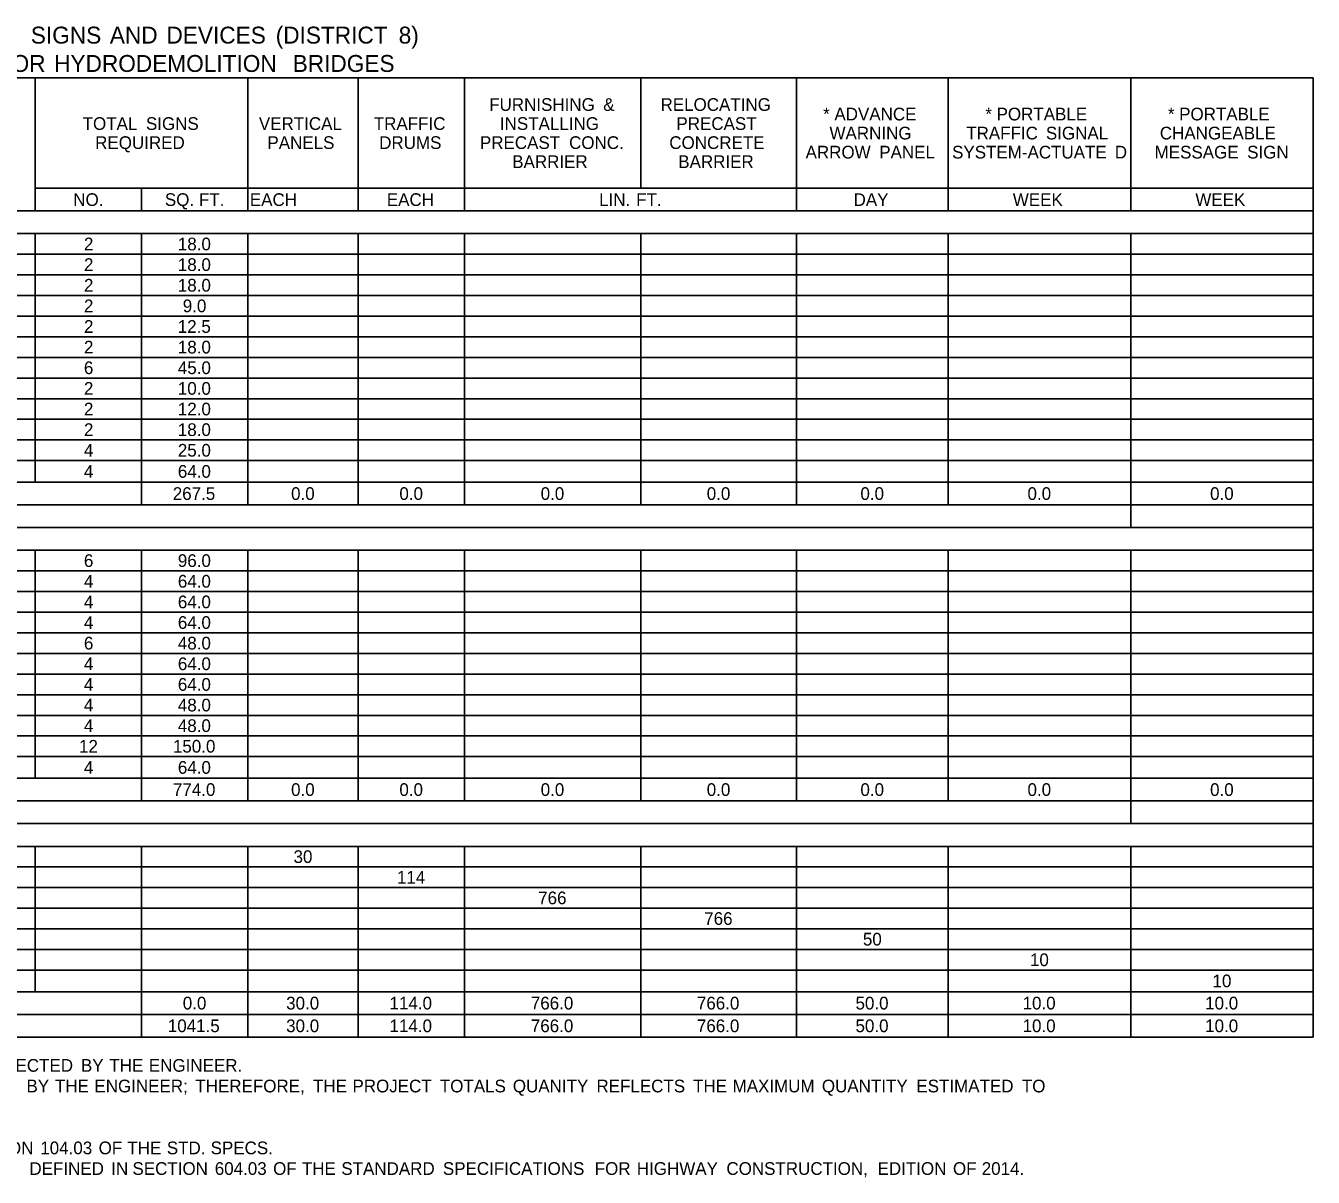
# Model space of a CAD drawing. Extents: x 540541 to 1930787, y -1948574 to 596640.
# Drawn here: x 542992 to 543601, y -1946816 to -1946271 of the extents above; entities that cross this region are included whole.
import ezdxf

# ---------------------------------------------------------------- set-up
doc = ezdxf.new("R2010")
doc.units = 0
doc.layers.add('Default', color=7, linetype='Continuous')

msp = doc.modelspace()

# ---------------------------------------------------------------- linework, layer by layer
at = {"layer": 'Default'}
for p, q in [((542470.09, -1946295.96), (543600.6, -1946295.96)), ((542996.59, -1946358.85), (542996.59, -1946295.96)), ((543097.02, -1946358.85), (543097.02, -1946295.96)), ((543149.18, -1946358.85), (543149.18, -1946295.96)), ((543199.39, -1946358.85), (543199.39, -1946295.96)), ((543282.75, -1946348.12), (543282.75, -1946295.96)), ((543356.37, -1946358.85), (543356.37, -1946295.96)), ((543428.03, -1946358.85), (543428.03, -1946295.96)), ((543514.32, -1946358.85), (543514.32, -1946295.96)), ((543600.6, -1946348.12), (543600.6, -1946295.96)), ((542996.59, -1946348.12), (543600.6, -1946348.12)), ((543046.8, -1946358.85), (543046.8, -1946348.12)), ((543149.18, -1946358.85), (543149.18, -1946348.12)), ((543514.32, -1946358.85), (543514.32, -1946348.12)), ((543600.6, -1946369.57), (543600.6, -1946348.12)), ((542470.09, -1946358.85), (543600.6, -1946358.85)), ((542938.58, -1946358.85), (543600.6, -1946358.85)), ((542470.09, -1946369.57), (543600.6, -1946369.57)), ((542996.59, -1946487.06), (542996.59, -1946369.57)), ((543046.8, -1946487.06), (543046.8, -1946369.57)), ((543046.8, -1946497.78), (543046.8, -1946369.57)), ((543097.02, -1946497.78), (543097.02, -1946369.57)), ((543097.02, -1946497.78), (543097.02, -1946369.57)), ((543149.18, -1946447.57), (543149.18, -1946369.57)), ((543149.18, -1946497.78), (543149.18, -1946369.57)), ((543199.39, -1946497.78), (543199.39, -1946369.57)), ((543199.39, -1946497.78), (543199.39, -1946369.57)), ((543282.75, -1946497.78), (543282.75, -1946369.57)), ((543282.75, -1946497.78), (543282.75, -1946369.57)), ((543356.37, -1946497.78), (543356.37, -1946369.57)), ((543356.37, -1946497.78), (543356.37, -1946369.57)), ((543428.03, -1946497.78), (543428.03, -1946369.57)), ((543514.32, -1946508.51), (543514.32, -1946369.57)), ((543600.6, -1946508.51), (543600.6, -1946369.57)), ((542470.09, -1946379.32), (543600.6, -1946379.32)), ((542470.09, -1946389.07), (543600.6, -1946389.07)), ((542470.09, -1946398.82), (543600.6, -1946398.82)), ((542470.09, -1946408.57), (543600.6, -1946408.57)), ((542470.09, -1946418.32), (543600.6, -1946418.32)), ((542470.09, -1946428.07), (543600.6, -1946428.07)), ((542470.09, -1946437.82), (543600.6, -1946437.82)), ((542470.09, -1946447.57), (543600.6, -1946447.57)), ((542470.09, -1946457.32), (543600.6, -1946457.32)), ((543149.18, -1946497.78), (543149.18, -1946457.32)), ((542470.09, -1946467.07), (543600.6, -1946467.07)), ((542470.09, -1946476.82), (543600.6, -1946476.82)), ((542470.09, -1946487.06), (543600.6, -1946487.06)), ((542470.09, -1946487.06), (543600.6, -1946487.06)), ((543428.03, -1946497.78), (543428.03, -1946487.06)), ((542470.09, -1946497.78), (543600.6, -1946497.78)), ((543514.32, -1946508.51), (543514.32, -1946497.78)), ((542470.09, -1946508.51), (543600.6, -1946508.51)), ((543600.6, -1946519.23), (543600.6, -1946508.51)), ((542470.09, -1946519.23), (543600.6, -1946519.23)), ((542996.59, -1946626.97), (542996.59, -1946519.23)), ((543046.8, -1946637.7), (543046.8, -1946519.23)), ((543046.8, -1946637.7), (543046.8, -1946519.23)), ((543097.02, -1946637.7), (543097.02, -1946519.23)), ((543097.02, -1946637.7), (543097.02, -1946519.23)), ((543149.18, -1946637.7), (543149.18, -1946519.23)), ((543149.18, -1946637.7), (543149.18, -1946519.23)), ((543199.39, -1946637.7), (543199.39, -1946519.23)), ((543199.39, -1946637.7), (543199.39, -1946519.23)), ((543282.75, -1946637.7), (543282.75, -1946519.23)), ((543282.75, -1946637.7), (543282.75, -1946519.23)), ((543356.37, -1946637.7), (543356.37, -1946519.23)), ((543356.37, -1946637.7), (543356.37, -1946519.23)), ((543428.03, -1946637.7), (543428.03, -1946519.23)), ((543514.32, -1946648.42), (543514.32, -1946519.23)), ((543600.6, -1946749.33), (543600.6, -1946519.23)), ((542470.09, -1946528.98), (543600.6, -1946528.98)), ((542470.09, -1946538.73), (543600.6, -1946538.73)), ((542470.09, -1946548.48), (543600.6, -1946548.48)), ((542470.09, -1946558.23), (543600.6, -1946558.23)), ((542470.09, -1946567.98), (543600.6, -1946567.98)), ((542470.09, -1946577.73), (543600.6, -1946577.73)), ((542470.09, -1946587.48), (543600.6, -1946587.48)), ((542470.09, -1946597.23), (543600.6, -1946597.23)), ((542470.09, -1946606.98), (543600.6, -1946606.98)), ((542470.09, -1946616.73), (543600.6, -1946616.73)), ((542470.09, -1946626.97), (543600.6, -1946626.97)), ((543097.02, -1946626.97), (543600.6, -1946626.97)), ((543428.03, -1946637.7), (543428.03, -1946626.97)), ((542470.09, -1946637.7), (543600.6, -1946637.7)), ((543514.32, -1946648.42), (543514.32, -1946637.7)), ((542470.09, -1946648.42), (543600.6, -1946648.42)), ((542470.09, -1946659.15), (543600.6, -1946659.15)), ((542996.59, -1946727.88), (542996.59, -1946659.15)), ((543046.8, -1946749.33), (543046.8, -1946659.15)), ((543046.8, -1946749.33), (543046.8, -1946659.15)), ((543097.02, -1946749.33), (543097.02, -1946659.15)), ((543097.02, -1946749.33), (543097.02, -1946659.15)), ((543149.18, -1946749.33), (543149.18, -1946659.15)), ((543149.18, -1946749.33), (543149.18, -1946659.15)), ((543199.39, -1946749.33), (543199.39, -1946659.15)), ((543199.39, -1946749.33), (543199.39, -1946659.15)), ((543282.75, -1946707.9), (543282.75, -1946659.15)), ((543282.75, -1946749.33), (543282.75, -1946659.15)), ((543356.37, -1946678.65), (543356.37, -1946659.15)), ((543356.37, -1946749.33), (543356.37, -1946659.15)), ((543428.03, -1946749.33), (543428.03, -1946659.15)), ((543514.32, -1946749.33), (543514.32, -1946659.15)), ((542470.09, -1946668.9), (543600.6, -1946668.9)), ((542470.09, -1946678.65), (543600.6, -1946678.65)), ((542938.58, -1946688.4), (543282.75, -1946688.4)), ((542996.59, -1946688.4), (543199.39, -1946688.4)), ((543199.39, -1946688.4), (543600.6, -1946688.4)), ((543356.37, -1946749.33), (543356.37, -1946688.4)), ((542470.09, -1946698.15), (543600.6, -1946698.15)), ((542470.09, -1946707.9), (543600.6, -1946707.9)), ((542470.09, -1946717.65), (543600.6, -1946717.65)), ((543282.75, -1946749.33), (543282.75, -1946717.65)), ((542470.09, -1946727.88), (543514.32, -1946727.88)), ((542470.09, -1946727.88), (543600.6, -1946727.88)), ((543428.03, -1946749.33), (543428.03, -1946727.88)), ((543514.32, -1946727.88), (543600.6, -1946727.88)), ((542470.09, -1946738.61), (543600.6, -1946738.61)), ((542470.09, -1946749.33), (543600.6, -1946749.33))]:
    msp.add_line(p, q, dxfattribs=at)

# ---------------------------------------------------------------- texts
for s, height, p in [(' SIGNS', 8, (542991.5, -1946279.73)), (' AND', 8, (543028.84, -1946279.73)), (' DEVICES', 8, (543055.61, -1946279.73)), (' (DISTRICT', 8, (543107.24, -1946279.73)), (' 8)', 8, (543165.37, -1946279.73)), (' FOR', 8, (542975.87, -1946293.13)), (' HYDRODEMOLITION', 8, (543002.51, -1946293.13)), (' BRIDGES', 8, (543115.26, -1946293.13)), ('FURNISHING', 6, (543211.12, -1946311.54)), (' &', 6, (543262.78, -1946311.54)), ('RELOCATING', 6, (543292.1, -1946311.54)), ('*', 6, (543368.97, -1946316.04)), (' ADVANCE', 6, (543372.05, -1946316.04)), ('*', 6, (543445.62, -1946316.04)), (' PORTABLE', 6, (543448.7, -1946316.04)), ('*', 6, (543531.91, -1946316.04)), (' PORTABLE', 6, (543534.99, -1946316.04)), ('TOTAL', 6, (543018.96, -1946320.54)), (' SIGNS', 6, (543046.65, -1946320.54)), ('VERTICAL', 6, (543102.26, -1946320.54)), ('TRAFFIC', 6, (543156.57, -1946320.54)), ('INSTALLING', 6, (543216.18, -1946320.54)), ('PRECAST', 6, (543299.61, -1946320.54)), ('WARNING', 6, (543371.96, -1946325.04)), ('TRAFFIC', 6, (543436.58, -1946325.04)), (' SIGNAL', 6, (543472.01, -1946325.04)), ('CHANGEABLE', 6, (543528.09, -1946325.04)), ('REQUIRED', 6, (543024.88, -1946329.54)), ('PANELS', 6, (543106.3, -1946329.54)), ('DRUMS', 6, (543159.12, -1946329.54)), ('PRECAST', 6, (543206.74, -1946329.54)), (' CONC.', 6, (543246.64, -1946329.54)), ('CONCRETE', 6, (543296.24, -1946329.54)), ('ARROW', 6, (543360.66, -1946334.04)), (' PANEL', 6, (543393.25, -1946334.04)), ('SYSTEM-ACTUATE', 6, (543429.9, -1946334.04)), ('D', 6, (543506.81, -1946334.04)), ('MESSAGE', 6, (543525.63, -1946334.04)), (' SIGN', 6, (543567.14, -1946334.04)), ('BARRIER', 6, (543222, -1946338.54)), ('BARRIER', 6, (543300.48, -1946338.54)), ('NO.', 6, (543014.53, -1946356.48)), ('SQ.', 6, (543057.82, -1946356.48)), (' FT.', 6, (543071.68, -1946356.48)), ('EACH', 6, (543097.99, -1946356.48)), ('EACH', 6, (543162.73, -1946356.48)), ('LIN.', 6, (543263.09, -1946356.48)), (' FT.', 6, (543278.35, -1946356.48)), ('DAY', 6, (543383.34, -1946356.48)), ('WEEK', 6, (543458.6, -1946356.48)), ('WEEK', 6, (543544.89, -1946356.48)), ('2', 6, (543019.59, -1946377.45)), ('18.0', 6, (543063.96, -1946377.45)), ('2', 6, (543019.59, -1946387.2)), ('18.0', 6, (543063.96, -1946387.2)), ('2', 6, (543019.59, -1946396.95)), ('18.0', 6, (543063.96, -1946396.95)), ('2', 6, (543019.59, -1946406.7)), ('9.0', 6, (543066.29, -1946406.7)), ('2', 6, (543019.59, -1946416.45)), ('12.5', 6, (543063.92, -1946416.45)), ('2', 6, (543019.59, -1946426.2)), ('18.0', 6, (543063.96, -1946426.2)), ('6', 6, (543019.56, -1946435.95)), ('45.0', 6, (543063.96, -1946435.95)), ('2', 6, (543019.59, -1946445.7)), ('10.0', 6, (543063.96, -1946445.7)), ('2', 6, (543019.59, -1946455.45)), ('12.0', 6, (543063.96, -1946455.45)), ('2', 6, (543019.59, -1946465.2)), ('18.0', 6, (543063.96, -1946465.2)), ('4', 6, (543019.57, -1946474.95)), ('25.0', 6, (543063.96, -1946474.95)), ('4', 6, (543019.57, -1946484.94)), ('64.0', 6, (543063.96, -1946484.94)), ('267.5', 6, (543061.55, -1946495.42)), ('0.0', 6, (543117.48, -1946495.42)), ('0.0', 6, (543168.67, -1946495.42)), ('0.0', 6, (543235.45, -1946495.42)), ('0.0', 6, (543313.94, -1946495.42)), ('0.0', 6, (543386.58, -1946495.42)), ('0.0', 6, (543465.55, -1946495.42)), ('0.0', 6, (543551.84, -1946495.42)), ('6', 6, (543019.56, -1946527.11)), ('96.0', 6, (543063.96, -1946527.11)), ('4', 6, (543019.57, -1946536.86)), ('64.0', 6, (543063.96, -1946536.86)), ('4', 6, (543019.57, -1946546.61)), ('64.0', 6, (543063.96, -1946546.61)), ('4', 6, (543019.57, -1946556.36)), ('64.0', 6, (543063.96, -1946556.36)), ('6', 6, (543019.56, -1946566.11)), ('48.0', 6, (543063.96, -1946566.11)), ('4', 6, (543019.57, -1946575.86)), ('64.0', 6, (543063.96, -1946575.86)), ('4', 6, (543019.57, -1946585.61)), ('64.0', 6, (543063.96, -1946585.61)), ('4', 6, (543019.57, -1946595.36)), ('48.0', 6, (543063.96, -1946595.36)), ('4', 6, (543019.57, -1946605.11)), ('48.0', 6, (543063.96, -1946605.11)), ('12', 6, (543017.26, -1946614.86)), ('150.0', 6, (543061.63, -1946614.86)), ('4', 6, (543019.57, -1946624.85)), ('64.0', 6, (543063.96, -1946624.85)), ('774.0', 6, (543061.63, -1946635.33)), ('0.0', 6, (543117.48, -1946635.33)), ('0.0', 6, (543168.67, -1946635.33)), ('0.0', 6, (543235.45, -1946635.33)), ('0.0', 6, (543313.94, -1946635.33)), ('0.0', 6, (543386.58, -1946635.33)), ('0.0', 6, (543465.55, -1946635.33)), ('0.0', 6, (543551.84, -1946635.33)), ('30', 6, (543118.64, -1946667.02)), ('114', 6, (543167.5, -1946676.77)), ('766', 6, (543234.27, -1946686.52)), ('766', 6, (543312.76, -1946696.27)), ('50', 6, (543387.74, -1946706.02)), ('10', 6, (543466.71, -1946715.77)), ('10', 6, (543553, -1946725.76)), ('0.0', 6, (543066.29, -1946736.25)), ('30.0', 6, (543115.15, -1946736.25)), ('114.0', 6, (543164.01, -1946736.25)), ('766.0', 6, (543230.79, -1946736.25)), ('766.0', 6, (543309.28, -1946736.25)), ('50.0', 6, (543384.25, -1946736.25)), ('10.0', 6, (543463.22, -1946736.25)), ('10.0', 6, (543549.51, -1946736.25)), ('1041.5', 6, (543059.22, -1946746.97)), ('30.0', 6, (543115.15, -1946746.97)), ('114.0', 6, (543164.01, -1946746.97)), ('766.0', 6, (543230.79, -1946746.97)), ('766.0', 6, (543309.28, -1946746.97)), ('50.0', 6, (543384.25, -1946746.97)), ('10.0', 6, (543463.22, -1946746.97)), ('10.0', 6, (543549.51, -1946746.97)), (' DIRECTED', 6, (542971.19, -1946765.68)), (' BY', 6, (543015.92, -1946765.68)), (' THE', 6, (543029.37, -1946765.68)), (' ENGINEER.', 6, (543048.02, -1946765.68)), (' BY', 6, (542990.19, -1946775.43)), (' THE', 6, (543003.64, -1946775.43)), (' ENGINEER;', 6, (543022.29, -1946775.43)), (' THEREFORE,', 6, (543070, -1946775.43)), (' THE', 6, (543125.62, -1946775.43)), (' PROJECT', 6, (543144.26, -1946775.43)), (' TOTALS', 6, (543185.56, -1946775.43)), (' QUANITY', 6, (543220.06, -1946775.43)), (' REFLECTS', 6, (543259.59, -1946775.43)), (' THE', 6, (543305.27, -1946775.43)), (' MAXIMUM', 6, (543323.92, -1946775.43)), (' QUANTITY', 6, (543366.13, -1946775.43)), (' ESTIMATED', 6, (543410.78, -1946775.43)), (' TO', 6, (543460.65, -1946775.43)), (' SECTION', 6, (542957.8, -1946804.68)), (' 104.03', 6, (542996.71, -1946804.68)), (' OF', 6, (543024.29, -1946804.68)), (' THE', 6, (543037.87, -1946804.68)), (' STD.', 6, (543056.52, -1946804.68)), (' SPECS.', 6, (543077.22, -1946804.68)), (' DEFINED', 6, (542991.57, -1946814.43)), (' IN', 6, (543030.25, -1946814.43)), (' SECTION', 6, (543040.28, -1946814.43)), (' 604.03', 6, (543079.18, -1946814.43)), (' OF', 6, (543106.76, -1946814.43)), (' THE', 6, (543120.35, -1946814.43)), (' STANDARD', 6, (543139, -1946814.43)), (' SPECIFICATIONS', 6, (543187, -1946814.43)), (' FOR', 6, (543258.76, -1946814.43)), (' HIGHWAY', 6, (543278.67, -1946814.43)), (' CONSTRUCTION,', 6, (543321, -1946814.43)), (' EDITION', 6, (543392.44, -1946814.43)), (' OF', 6, (543428.08, -1946814.43)), (' 2014.', 6, (543441.67, -1946814.43))]:
    msp.add_text(s, height=height, dxfattribs=at).set_placement(p)

doc.saveas('drawing.dxf')
